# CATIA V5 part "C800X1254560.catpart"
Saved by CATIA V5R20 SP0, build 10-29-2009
Part number: C800X1254560
Source: Unknown
Property "A": "50"
Property "ARTICLENO": "C800X1254560"
Property "B": "23"
Property "BOMINFO": "C800X1254560"
Property "C": "91"
Property "CA": "C800X1254560"
Property "D1": "90"
Property "DES": "ROTATING EYEBOLT WITH RING Ton 12,5 M45x60"
Property "E": "86"
Property "H": "200"
Property "L": "60"
Property "LINA": "C800X1254560"
Property "NB": "C800X1254560"
Property "NBSYN": "$CODE."
Property "NN": "C800X"
Property "NT": "Rotating eyebolt with ring"
Property "SIZE": "M45"
Property "SUPPLIER": "CF"
Property "SW": "80"
Property "WEIGHT": "5200"
Property "WLL": "12.50"
Bounding box of the stored display mesh (mm): x -47.825 to 48, y -60 to 222.825, z -45 to 45
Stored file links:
  C:\Users\Utente\Desktop\3D files 800X\C800X1254560.catpart

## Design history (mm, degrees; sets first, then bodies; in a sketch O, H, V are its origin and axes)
Body1 "Geometry.1" (main body)
  Solid1 "C800X1254560.catpart": solid without history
